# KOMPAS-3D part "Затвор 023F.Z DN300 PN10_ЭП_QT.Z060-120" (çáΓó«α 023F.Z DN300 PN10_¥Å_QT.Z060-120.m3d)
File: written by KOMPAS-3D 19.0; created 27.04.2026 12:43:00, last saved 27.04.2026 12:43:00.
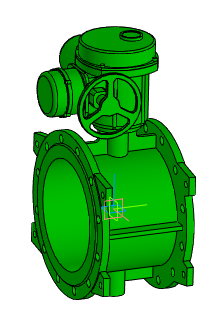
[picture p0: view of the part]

Document properties: Полное имя файла: Затвор 023F.Z DN300 PN10 + электропривод QT.Z060-120.a3d

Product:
- Part/product: Затвор 023F.Z DN300 PN10_ЭП_QT.Z060-120
    Масса: 151.642
  - Body: Тело 1
      Масса: 151.944

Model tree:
1. Операция без истории:1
